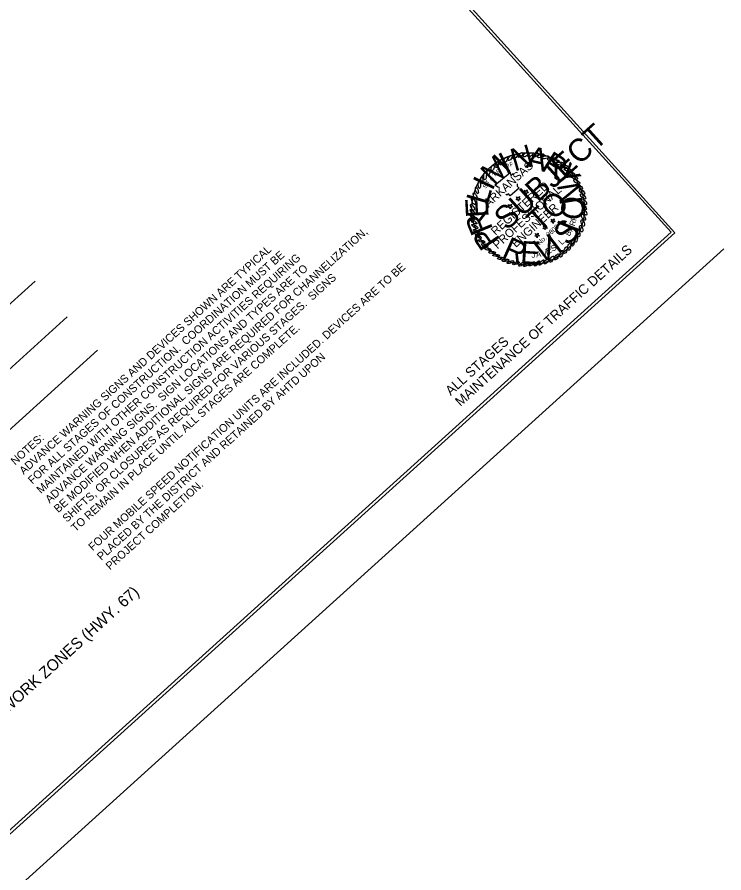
# Model space of a CAD drawing. Extents: x 1307930 to 1312775, y 238372 to 242903.
# Drawn here: x 1309391 to 1309973, y 239039 to 239743 of the extents above; entities that cross this region are included whole.
import ezdxf

# ---------------------------------------------------------------- set-up
doc = ezdxf.new("R2010")
doc.units = 0
for name, color, linetype in [('R_Annotation', 7, 'Continuous'), ('R_Border', 7, 'Continuous'), ('R_Border Notes', 7, 'Continuous'), ('R_Border PE', 7, 'Continuous'), ('R_Border Prem', 7, 'Continuous'), ('R_Draft', 7, 'Continuous'), ('R_No Plot', 7, 'Continuous')]:
    doc.layers.add(name, color=color, linetype=linetype)

msp = doc.modelspace()

# ---------------------------------------------------------------- linework, layer by layer
at = {"layer": 'R_Border'}
for p, q in [((1309929.31, 239566.22), (1309240.18, 240328.09)), ((1309929.31, 239566.22), (1308756.77, 238505.7)), ((1308667.51, 238371.76), (1309972.8, 239552.5))]:
    msp.add_line(p, q, dxfattribs=at)
at = {"layer": 'R_Border PE'}
for points in [[(1309787.42, 239603.13), (1309784.47, 239604.84), (1309796.86, 239615.44), (1309797.44, 239613), (1309799.4, 239614.57), (1309799.49, 239614.24)], [(1309802.76, 239606.01), (1309802.73, 239604.03), (1309804.46, 239602.56), (1309797.03, 239596.24), (1309795.62, 239597.8), (1309794.32, 239596.63), (1309793.45, 239597.59)]]:
    msp.add_lwpolyline(points, dxfattribs=at)
for points in [[(1309802.32, 239595.23), (1309803.53, 239594.57), (1309804.53, 239595.48), (1309804.35, 239594.1), (1309805.59, 239593.41), (1309804.2, 239593.16), (1309803.81, 239591.8), (1309803.24, 239593.1), (1309801.78, 239592.99), (1309802.86, 239593.97)], [(1309808.69, 239600.79), (1309810, 239600.02), (1309811.07, 239600.99), (1309810.72, 239599.66), (1309812.06, 239598.85), (1309810.57, 239598.71), (1309810.28, 239597.24), (1309809.61, 239598.66), (1309808.22, 239598.41), (1309809.33, 239599.41)], [(1309795.64, 239588.98), (1309796.94, 239588.21), (1309798.02, 239589.18), (1309797.63, 239587.82), (1309798.97, 239587.01), (1309797.51, 239586.91), (1309797.23, 239585.44), (1309796.56, 239586.85), (1309795.16, 239586.6), (1309796.27, 239587.61)], [(1309830.76, 239577.06), (1309832.1, 239576.25), (1309833.17, 239577.22), (1309832.79, 239575.93), (1309834.09, 239575.09), (1309832.63, 239574.99), (1309832.35, 239573.51), (1309831.68, 239574.93), (1309830.32, 239574.64), (1309831.43, 239575.65)], [(1309824.39, 239571.51), (1309825.63, 239570.81), (1309826.63, 239571.71), (1309826.31, 239570.28), (1309827.66, 239569.68), (1309826.27, 239569.43), (1309825.88, 239568.07), (1309825.31, 239569.37), (1309823.89, 239569.23), (1309824.96, 239570.2)], [(1309817.7, 239565.26), (1309819.01, 239564.41), (1309820.12, 239565.42), (1309819.7, 239564.09), (1309821.04, 239563.28), (1309819.58, 239563.18), (1309819.3, 239561.71), (1309818.62, 239563.12), (1309817.26, 239562.84), (1309818.38, 239563.84)]]:
    msp.add_lwpolyline(points, close=True, dxfattribs=at)
for centre, major_axis, ratio in [((1309796.9, 239627.25), (-1.47, -1.94), 0.475469), ((1309801, 239628.56), (-1.66, -1.78), 0.475469), ((1309805.52, 239629.75), (-1.66, -1.78), 0.475469), ((1309809.7, 239630.06), (-1.84, -1.59), 0.475469), ((1309813.57, 239629.98), (-2.12, -1.45), 0.451028), ((1309818.03, 239629.75), (-2.31, -1.3), 0.436264), ((1309822.09, 239629.12), (-2.5, -1.19), 0.418512), ((1309826.08, 239627.89), (-2.78, -0.65), 0.40589), ((1309786.06, 239621.69), (-0.74, -2.32), 0.475469), ((1309789.56, 239623.87), (-0.74, -2.32), 0.475469), ((1309793.17, 239625.81), (-1.22, -2.1), 0.475469), ((1309830.59, 239626.63), (-2.83, -0.35), 0.40589), ((1309834.42, 239624.71), (-2.85, -0.05), 0.40589), ((1309838.02, 239622.69), (-2.85, -0.05), 0.40589), ((1309776.29, 239612.55), (-0.29, -3.1), 0.348728), ((1309779.22, 239615.55), (-0.42, -2.42), 0.44237), ((1309782.54, 239619.1), (-0.74, -2.32), 0.475469), ((1309841.23, 239620.43), (-2.85, 0.09), 0.40589), ((1309844.34, 239617.63), (-2.81, 0.49), 0.40589), ((1309847.18, 239614.61), (-2.7, 0.92), 0.40589), ((1309773.66, 239608.95), (0.13, -2.85), 0.329518), ((1309849.85, 239611.28), (-2.6, 1.16), 0.40589), ((1309851.73, 239607.7), (-2.4, 1.55), 0.40589), ((1309769.62, 239600.65), (0.81, -2.73), 0.329518), ((1309771.63, 239605.13), (0.16, -2.85), 0.329518), ((1309854.24, 239603.57), (-2.26, 1.74), 0.40589), ((1309856.11, 239599.44), (-2.03, 2), 0.40589), ((1309766.74, 239591.7), (1.27, -2.55), 0.394697), ((1309768.16, 239596.04), (1.27, -2.55), 0.375751), ((1309856.99, 239595.65), (-2.03, 2), 0.40589), ((1309765.91, 239586.71), (1.27, -2.55), 0.391724), ((1309857.86, 239591.33), (-1.81, 2.2), 0.40589), ((1309857.84, 239587.14), (-1.55, 2.39), 0.40589), ((1309766.05, 239582.72), (1.91, -2.12), 0.322879), ((1309766.3, 239578.88), (1.91, -2.12), 0.322879), ((1309857.21, 239578.56), (-1.35, 2.51), 0.40589), ((1309858.15, 239582.68), (-1.55, 2.39), 0.40589), ((1309767.09, 239574.73), (2.42, -1.51), 0.322879), ((1309767.93, 239570.99), (2.42, -1.51), 0.322879), ((1309856.63, 239573.72), (-0.92, 2.7), 0.40589), ((1309769.28, 239566.87), (2.42, -1.51), 0.322879), ((1309853.18, 239565.29), (-0.28, 2.84), 0.40589), ((1309855.37, 239569.13), (-0.83, 2.73), 0.40589), ((1309770.82, 239562.83), (2.42, -1.51), 0.322879), ((1309773.38, 239558.79), (2.75, -0.77), 0.322879), ((1309848.54, 239557.65), (0.38, 2.83), 0.40589), ((1309851.22, 239561), (0.18, 2.85), 0.40589), ((1309775.9, 239555.63), (2.75, -0.77), 0.322879), ((1309778.54, 239552.34), (2.75, -0.77), 0.322879), ((1309842.55, 239551.47), (0.85, 2.72), 0.40589), ((1309845.58, 239554.16), (0.6, 2.79), 0.40589), ((1309781.96, 239549.59), (2.84, -0.22), 0.322879), ((1309785.45, 239547.14), (2.84, -0.22), 0.322879), ((1309789.36, 239544.72), (2.85, 0.05), 0.322879), ((1309826.77, 239542.29), (1.95, 2.08), 0.40589), ((1309831.26, 239544.04), (1.53, 2.41), 0.40589), ((1309835.22, 239545.84), (1.53, 2.41), 0.40589), ((1309839.11, 239548.43), (0.85, 2.72), 0.40589), ((1309793.12, 239543.05), (2.83, 0.35), 0.322879), ((1309797.26, 239541.62), (2.74, 0.8), 0.322879), ((1309801.67, 239540.68), (2.74, 0.8), 0.322879), ((1309806.47, 239539.88), (2.47, 1.43), 0.322879), ((1309810.51, 239539.63), (2.47, 1.43), 0.322879), ((1309814.81, 239540.13), (2.47, 1.43), 0.322879), ((1309819.07, 239540.5), (1.95, 2.08), 0.322879), ((1309822.85, 239541.29), (1.95, 2.08), 0.322879)]:
    msp.add_ellipse(centre, major_axis=major_axis, ratio=ratio, dxfattribs=at)
at = {"layer": 'R_Border Prem'}
msp.add_circle((1309811.72, 239585.38), 46.29, dxfattribs=at)
at = {"layer": 'R_Draft'}
for p, q in [((1309406.06, 239525.88), (1309199.86, 239339.35)), ((1309225.76, 239309.5), (1309432.57, 239496.58)), ((1309457.47, 239469.05), (1309251.26, 239282.53))]:
    msp.add_line(p, q, dxfattribs=at)
at = {"layer": 'R_No Plot'}
msp.add_lwpolyline([(1308757.05, 238502.44), (1309932.49, 239565.66), (1309239.87, 240331.45), (1308064.4, 239268.13)], close=True, dxfattribs=at)

# ---------------------------------------------------------------- texts
at = {"layer": 'R_Annotation'}
for s, height, p in [('BE MODIFIED WHEN ADDITIONAL SIGNS ARE REQUIRED FOR CHANNELIZATION,', 6.5881, (1309425.2, 239334.91)), ('ADVANCE WARNING SIGNS AND DEVICES SHOWN ARE TYPICAL', 6.5881, (1309396.79, 239366.31)), ('FOR ALL STAGES OF CONSTRUCTION.  COORDINATION MUST BE ', 6.5881, (1309403.9, 239358.46)), ('MAINTAINED WITH OTHER CONSTRUCTION ACTIVITIES REQUIRING', 6.5881, (1309411, 239350.61)), ('ADVANCE WARNING SIGNS.  SIGN LOCATIONS AND TYPES ARE TO', 6.5881, (1309418.1, 239342.76)), ('FOUR MOBILE SPEED NOTIFICATION UNITS ARE INCLUDED. DEVICES ARE TO BE', 6.5881, (1309453.62, 239303.5)), ('SHIFTS, OR CLOSURES AS REQUIRED FOR VARIOUS STAGES.  SIGNS', 6.5881, (1309432.31, 239327.05)), ('TO REMAIN IN PLACE UNTIL ALL STAGES ARE COMPLETE.', 6.5881, (1309439.41, 239319.2)), ('PLACED BY THE DISTRICT AND RETAINED BY AHTD UPON', 6.5881, (1309460.72, 239295.64)), ('NOTES:', 6.588, (1309389.69, 239374.17)), ('PROJECT COMPLETION.', 6.5881, (1309467.82, 239287.79)), ('ADVANCE WARNING SIGNS AT BEGIN AND END WORK ZONES (HWY. 67)', 9.375, (1309166.1, 238973.44))]:
    msp.add_text(s, height=height, rotation=42.13177, dxfattribs=at).set_placement(p)
at = {"layer": 'R_Border Notes'}
for s, p in [('MAINTENANCE OF TRAFFIC DETAILS', (1309756.14, 239422.35)), ('ALL STAGES', (1309748.09, 239431.25))]:
    msp.add_text(s, height=8, rotation=42.12688, dxfattribs=at).set_placement(p)
at = {"layer": 'R_Border PE'}
for s, height, rotation, p in [('ARKANSAS', 6.907, 42.12851, (1309779.22, 239586.34)), ('O', 3.45, 24.75059, (1309793.54, 239618.44)), ('F', 3.45, 20.13068, (1309797.2, 239620.13)), ('T', 3.45, 43.23023, (1309784.16, 239611.37)), ('E', 3.45, 38.61032, (1309787.12, 239614.05)), ('T', 3.45, 57.08996, (1309779.14, 239605.21)), ('A', 3.45, 47.85014, (1309781.28, 239608.36)), ('S', 3.45, 61.70987, (1309777.2, 239601.84)), ('REGISTERED', 6.907, 42.12851, (1309784.96, 239563.22)), ('PROFESSIONAL', 6.9069, 42.12851, (1309786.52, 239552.02)), ('ENGINEER', 6.907, 42.12851, (1309801.66, 239553.18)), ('R', 4.8, 77.35043, (1309851.31, 239575.29)), ('R', 4.8, 71.75003, (1309849.99, 239570.86)), ('No. 9808', 3.946, 42.12851, (1309821.2, 239555.28)), ('B', 4.8, 60.54923, (1309845.71, 239562.47)), ('A', 4.8, 66.14963, (1309848.06, 239566.42)), ('L', 4.8, 43.74802, (1309839.51, 239555.45)), ('.', 4.8, 49.34842, (1309842.61, 239558.66)), ('M', 4.8, 15.74601, (1309823.27, 239546.43)), ('E', 4.8, 26.94681, (1309828.17, 239548.09)), ('S', 4.8, 32.54722, (1309832.09, 239550.02)), ('J', 4.8, 4.5452, (1309814.56, 239545.02)), ('A', 4.8, 10.14561, (1309818.58, 239545.42))]:
    msp.add_text(s, height=height, rotation=rotation, dxfattribs=at).set_placement(p)
at = {"layer": 'R_Border Prem'}
for s, rotation, p in [('SUBJECT', 42.12851, (1309794.21, 239567)), ('N', 15.84845, (1309800.4, 239616.14)), ('M', 44.82281, (1309783.92, 239603.87)), ('I', 25.50657, (1309793.47, 239612.92)), ('A', 346.8741, (1309809.1, 239619.57)), ('R', 327.55787, (1309821.38, 239618)), ('Y', 308.24163, (1309831.27, 239613.46)), ('I', 64.13904, (1309782.29, 239599.64)), ('N', 99.26627, (1309856.64, 239590.63)), ('E', 93.1134, (1309779.33, 239578.62)), ('L', 73.79716, (1309778.38, 239587.87)), ('TO', 42.12851, (1309821.27, 239565.11)), ('O', 78.70395, (1309855.67, 239574.79)), ('R', 112.42963, (1309783.16, 239568.87)), ('S', 47.86048, (1309844.56, 239554.35)), ('I', 68.42279, (1309852.12, 239564.63)), ('P', 124.73739, (1309789.51, 239559.98)), ('R', 335.89238, (1309789.16, 239545.98)), ('E', 356.4547, (1309804.89, 239540.52)), ('V', 17.01701, (1309820.26, 239540.74)), ('I', 37.57932, (1309836.38, 239547.36))]:
    msp.add_text(s, height=18.62, rotation=rotation, dxfattribs=at).set_placement(p)

doc.saveas('drawing.dxf')
